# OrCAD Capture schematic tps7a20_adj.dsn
size A
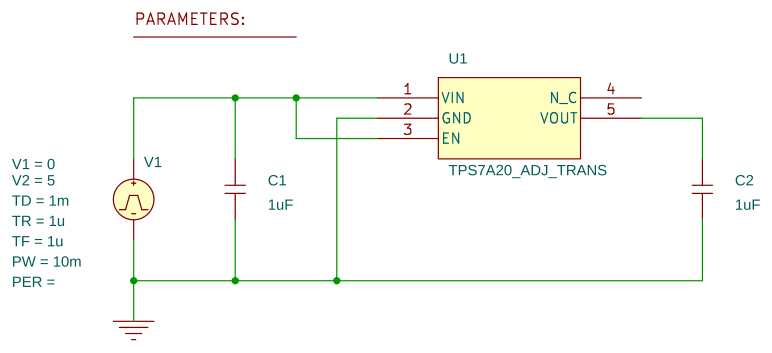
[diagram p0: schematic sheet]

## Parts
1  PARAM
C1  1uF  [cap196]
C2  1uF  [cap196]
U1  TPS7A20_ADJ_TRANS
V1  VPULSE

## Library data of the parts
1 = PARAM: V_out: 2.4V
C1 C2 = C
U1 = TPS7A20_ADJ_TRANS
V1 = VPULSE: PW: 10m; TD: 1m; TF: 1u; TR: 1u; V1: 0; V2: 5

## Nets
0: C1.1 C2.1 U1.2(GND) V1.2(-)
N00581: C1.2 U1.1(VIN) U1.3(EN) V1.1(+)
N00734: C2.2 U1.5(VOUT)

Not connected (* = marked no-connect by the designer): U1 4(N_C)
